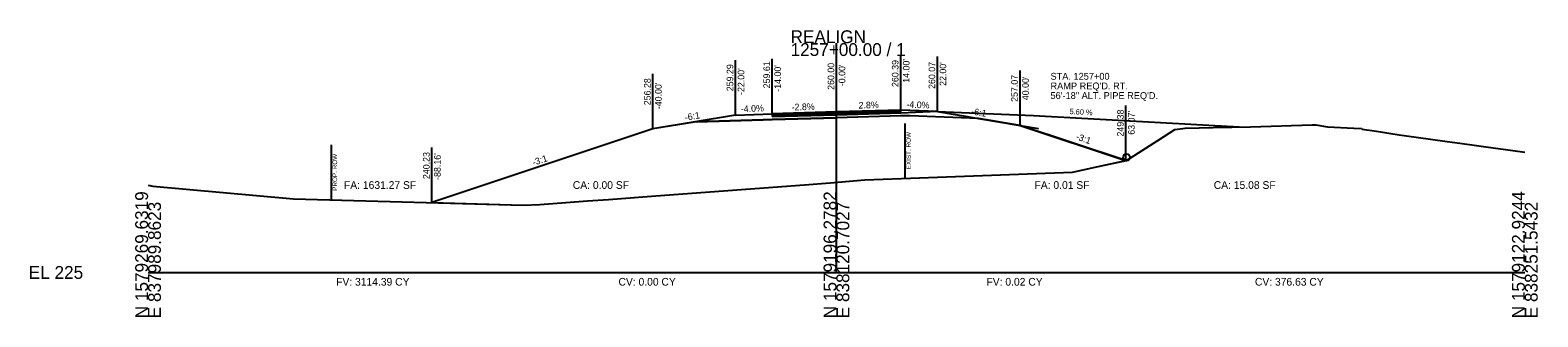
# Model space of a CAD drawing. Extents: x -26 to 6303, y -16 to 9563.
# Drawn here: x 2974.3 to 3302.8, y 8990.3 to 9052.8 of the extents above; entities that cross this region are included whole.
import ezdxf

# ---------------------------------------------------------------- set-up
doc = ezdxf.new("R2010")
doc.units = 0
for name, color, linetype in [('ASPHALT_19MM1', 7, 'Continuous'), ('ASPHALT_9_5MM1', 7, 'Continuous'), ('CONST_LV3', 7, 'Continuous'), ('CONST_PROF_LV1', 7, 'Continuous'), ('Draft_XS_Grid', 7, 'Continuous'), ('DTM_TEMP_DROP', 7, 'Continuous'), ('DTM_X_GROUND', 7, 'Continuous'), ('TRANS_BRIDGE', 7, 'Continuous'), ('XS_CELL', 7, 'Continuous'), ('XS_M_SHAPES_EARTHWORK', 7, 'Continuous'), ('XS_P_DRAINAGE', 7, 'Continuous'), ('XS_P_DRIVEWAY', 7, 'Continuous'), ('XS_P_GROUND', 7, 'Continuous'), ('XS_P_NULL_POINT', 7, 'Continuous'), ('XS_P_ROW', 7, 'Continuous'), ('XS_P_SHOULDER', 7, 'Continuous'), ('XS_P_SUBGRADE_GRANULAR', 7, 'Continuous'), ('XS_P_TX_CLEARZONE', 7, 'Continuous'), ('XS_P_TX_FS_BS', 7, 'Continuous'), ('XS_PLAN_CLEAR_ZONE', 7, 'Continuous'), ('XS_SHEET_EW_TX_AREA', 7, 'Continuous'), ('XS_SHEET_EW_TX_VOLUME', 7, 'Continuous'), ('XS_X_ROW', 7, 'Continuous')]:
    doc.layers.add(name, color=color, linetype=linetype)

msp = doc.modelspace()

# ---------------------------------------------------------------- linework, layer by layer
at = {"layer": 'ASPHALT_19MM1'}
msp.add_lwpolyline([(3136, 9034), (3136, 9034), (3136, 9034), (3150, 9034.39), (3150, 9034.39), (3164, 9034.79), (3164, 9034.79), (3164, 9035.06), (3150, 9034.66), (3150, 9034.66), (3136, 9034.27), (3136, 9034.27), (3136, 9034)], dxfattribs=at)
at = {"layer": 'ASPHALT_9_5MM1'}
msp.add_lwpolyline([(3136, 9034.48), (3136, 9034.48), (3136, 9034.48), (3150, 9034.87), (3150, 9034.87), (3164, 9035.26), (3164, 9035.26), (3164, 9035.39), (3150, 9035), (3150, 9035), (3136, 9034.61), (3136, 9034.61), (3136, 9034.48)], dxfattribs=at)
at = {"layer": 'CONST_LV3'}
for points in [[(3150, 9035), (3164, 9034.72)], [(3172, 9035.07), (3164, 9034.72), (3164, 9034.72)], [(3119.53, 9032.87), (3110, 9031.28)], [(3180.96, 9033.58), (3194, 9031.4)]]:
    msp.add_lwpolyline(points, dxfattribs=at)
at = {"layer": 'DTM_X_GROUND'}
msp.add_lwpolyline([(3000, 9019.04), (3001.05, 9018.78), (3031.7, 9016.03), (3081.64, 9014.7), (3085.4, 9014.85), (3095.72, 9015.59), (3100.34, 9015.93), (3110.61, 9016.69), (3143.07, 9019.07), (3148.65, 9019.53), (3156.22, 9020.17), (3164.2, 9020.47), (3201.46, 9021.88), (3207.05, 9023.08), (3213.18, 9024.4), (3220.06, 9028.8), (3223.76, 9031.15), (3225.46, 9031.38), (3226.01, 9031.46), (3232.11, 9031.6), (3240.2, 9031.77), (3253.63, 9032.18), (3254.31, 9032.2), (3254.46, 9032.17), (3257.04, 9031.77), (3262.74, 9031.44), (3264.42, 9031.36), (3264.58, 9031.25), (3267.71, 9030.81), (3272.6, 9030.04), (3276.32, 9029.49), (3283.05, 9028.57), (3285.83, 9028.16), (3293.58, 9027.12), (3295.28, 9026.87), (3300, 9026.24)], dxfattribs=at)
at = {"layer": 'XS_CELL'}
for p, q in [((3150, 9000), (3150, 9050)), ((3000, 9000), (3150, 9000)), ((3150, 9000), (3300, 9000))]:
    msp.add_line(p, q, dxfattribs=at)
at = {"layer": 'XS_M_SHAPES_EARTHWORK'}
msp.add_lwpolyline([(3061.84, 9015.23), (3081.64, 9014.7), (3085.4, 9014.85), (3095.72, 9015.59), (3100.34, 9015.93), (3110.61, 9016.69), (3143.07, 9019.07), (3148.65, 9019.53), (3156.22, 9020.17), (3164.2, 9020.47), (3201.46, 9021.88), (3207.05, 9023.08), (3213.07, 9024.38), (3190, 9032.07), (3180.96, 9033.58), (3166, 9034.17), (3164, 9034.12), (3150, 9033.73), (3136, 9033.33), (3134, 9033.28), (3119.53, 9032.87), (3110, 9031.28)], close=True, dxfattribs=at)
at = {"layer": 'XS_P_DRAINAGE'}
msp.add_circle((3213.21, 9025.08), 0.75, dxfattribs=at)
at = {"layer": 'XS_P_DRIVEWAY'}
for p, q in [((3172, 9035.07), (3192.94, 9034.23)), ((3192.94, 9034.23), (3237.76, 9031.72))]:
    msp.add_line(p, q, dxfattribs=at)
at = {"layer": 'XS_P_GROUND'}
for points in [[(3172, 9035.07), (3190, 9032.07), (3213.07, 9024.38)], [(3172, 9035.07), (3190, 9032.07), (3213.21, 9024.33)], [(3128, 9034.29), (3110, 9031.28), (3061.84, 9015.23)]]:
    msp.add_lwpolyline(points, dxfattribs=at)
at = {"layer": 'XS_P_ROW'}
msp.add_line((3040, 9015.81), (3040, 9027.81), dxfattribs=at)
at = {"layer": 'XS_P_SHOULDER'}
for points in [[(3172, 9035.07), (3172, 9035.07), (3164, 9035.39)], [(3128, 9034.29), (3128, 9034.29), (3136, 9034.61)]]:
    msp.add_lwpolyline(points, dxfattribs=at)
at = {"layer": 'XS_P_SUBGRADE_GRANULAR'}
for points in [[(3119.53, 9032.87), (3119.53, 9032.87), (3134, 9033.28), (3134, 9033.28), (3136, 9033.33)], [(3136, 9033.33), (3136, 9033.33), (3150, 9033.73)], [(3164, 9034.12), (3150, 9033.73), (3150, 9033.73)], [(3180.96, 9033.58), (3180.96, 9033.58), (3166, 9034.17), (3164, 9034.12), (3164, 9034.12)]]:
    msp.add_lwpolyline(points, dxfattribs=at)
at = {"layer": 'XS_P_TX_CLEARZONE'}
for p, q in [((3128, 9034.29), (3128, 9046.29)), ((3136, 9034.61), (3136, 9046.61)), ((3150, 9035), (3150, 9047)), ((3164, 9035.39), (3164, 9047.39)), ((3172, 9035.07), (3172, 9047.07)), ((3172, 9035.07), (3172, 9047.07)), ((3110, 9031.28), (3110, 9043.28)), ((3190, 9032.07), (3190, 9044.07)), ((3213.07, 9024.38), (3213.07, 9036.38)), ((3061.84, 9015.23), (3061.84, 9027.23))]:
    msp.add_line(p, q, dxfattribs=at)
at = {"layer": 'XS_PLAN_CLEAR_ZONE'}
msp.add_lwpolyline([(3136, 9034.27), (3136, 9034.27), (3136, 9034.27), (3150, 9034.66), (3150, 9034.66), (3164, 9035.06), (3164, 9035.06), (3164, 9035.26), (3150, 9034.87), (3150, 9034.87), (3136, 9034.48), (3136, 9034.48), (3136, 9034.27)], dxfattribs=at)
at = {"layer": 'XS_X_ROW'}
msp.add_line((3165.01, 9020.5), (3165.01, 9032.5), dxfattribs=at)

# ---------------------------------------------------------------- texts
at = {"layer": 'CONST_PROF_LV1'}
for p in [(3212.99, 9024.26), (3061.76, 9015.11)]:
    msp.add_text('X', height=0.24, dxfattribs=at).set_placement(p)
at = {"layer": 'Draft_XS_Grid'}
msp.add_text('-', height=0.0001, dxfattribs=at).set_placement((3000, 9000))
at = {"layer": 'DTM_TEMP_DROP'}
for p in [(3135.92, 9034.49), (3149.92, 9034.88), (3163.92, 9035.27)]:
    msp.add_text('X', height=0.24, dxfattribs=at).set_placement(p)
at = {"layer": 'TRANS_BRIDGE'}
for p in [(3212.99, 9024.26), (3061.76, 9015.11)]:
    msp.add_text('X', height=0.24, dxfattribs=at).set_placement(p)
at = {"layer": 'XS_CELL'}
for s, p in [('REALIGN', (3140, 9050)), ('1257+00.00 / 1', (3140, 9047.2)), ('EL 225', (2974, 8998.6))]:
    msp.add_text(s, height=2.8, dxfattribs=at).set_placement(p)
for s, p in [('N 1579269.6319', (3000, 8990)), ('E 837989.8623', (3002.8, 8990)), ('N 1579196.2782', (3150, 8990)), ('E 838120.7027', (3152.8, 8990)), ('N 1579122.9244', (3300, 8990)), ('E 838251.5432', (3302.8, 8990))]:
    msp.add_text(s, height=2.8, rotation=90, dxfattribs=at).set_placement(p)
at = {"layer": 'XS_P_DRIVEWAY'}
for s, p in [('STA. 1257+00', (3196.64, 9042.02)), ("RAMP REQ'D. RT.", (3196.64, 9039.92)), ('56\'-18" ALT. PIPE REQ\'D.', (3196.64, 9037.82))]:
    msp.add_text(s, height=1.5, dxfattribs=at).set_placement(p)
msp.add_text('5.60 %', height=1.2, rotation=356.7923, dxfattribs=at).set_placement((3200.78, 9034.54))
at = {"layer": 'XS_P_GROUND'}
for p in [(3109.92, 9031.16), (3193.92, 9031.28)]:
    msp.add_text('X', height=0.24, dxfattribs=at).set_placement(p)
at = {"layer": 'XS_P_NULL_POINT'}
for p in [(3171.92, 9034.95), (3189.92, 9031.95)]:
    msp.add_text('X', height=0.24, dxfattribs=at).set_placement(p)
at = {"layer": 'XS_P_ROW'}
msp.add_text('PROP. ROW', height=1, rotation=90, dxfattribs=at).set_placement((3041.2, 9017.81))
at = {"layer": 'XS_P_SHOULDER'}
for p in [(3171.92, 9034.95), (3127.92, 9034.17)]:
    msp.add_text('X', height=0.24, dxfattribs=at).set_placement(p)
at = {"layer": 'XS_P_SUBGRADE_GRANULAR'}
msp.add_text('X', height=0.24, dxfattribs=at).set_placement((3213.13, 9024.21))
at = {"layer": 'XS_P_TX_CLEARZONE'}
for s, p in [('259.29', (3127.52, 9039.52)), ('259.61', (3135.52, 9040.15)), ("-14.00'", (3137.92, 9039.4)), ('260.00', (3149.52, 9039.82)), ("-0.00'", (3151.92, 9040.61)), ('260.39', (3163.52, 9040.44)), ("14.00'", (3165.92, 9041.36)), ('260.07', (3171.52, 9040.02)), ("22.00'", (3173.92, 9040.68)), ('256.28', (3109.52, 9036.46)), ("-40.00'", (3111.92, 9035.6)), ("-22.00'", (3129.92, 9038.71)), ('257.07', (3189.52, 9037.2)), ("40.00'", (3191.92, 9037.56)), ('249.38', (3212.59, 9029.63)), ("63.07'", (3214.99, 9030.03)), ('240.23', (3061.36, 9020.36)), ("-88.16'", (3063.76, 9020.18))]:
    msp.add_text(s, height=1.44, rotation=90, dxfattribs=at).set_placement(p)
at = {"layer": 'XS_P_TX_FS_BS'}
for s, rotation, p in [('-6:1', 9.4642, (3117.08, 9033.07)), ('-4.0%', 2.2906, (3129.18, 9034.93)), ('-2.8%', 1.6039, (3140.25, 9035.32)), ('2.8%', 1.6039, (3154.84, 9035.73)), ('-4.0%', 357.7094, (3165.23, 9035.94)), ('-6:1', 350.5377, (3179.28, 9034.47)), ('-3:1', 339.784, (3202.04, 9029.08)), ('-3:1', 18.4332, (3084.01, 9023.25))]:
    msp.add_text(s, height=1.44, rotation=rotation, dxfattribs=at).set_placement(p)
at = {"layer": 'XS_SHEET_EW_TX_AREA'}
for s, p in [('FA: 1631.27 SF', (3042.69, 9018.22)), ('CA: 0.00 SF', (3092.56, 9018.22)), ('FA: 0.01 SF', (3193.16, 9018.22)), ('CA: 15.08 SF', (3232.22, 9018.22))]:
    msp.add_text(s, height=1.68, dxfattribs=at).set_placement(p)
at = {"layer": 'XS_SHEET_EW_TX_VOLUME'}
for s, p in [('FV: 3114.39 CY', (3040.98, 8997.12)), ('CV: 0.00 CY', (3102.51, 8997.12)), ('FV: 0.02 CY', (3182.69, 8997.12)), ('CV: 376.63 CY', (3241.19, 8997.12))]:
    msp.add_text(s, height=1.68, dxfattribs=at).set_placement(p)
at = {"layer": 'XS_X_ROW'}
msp.add_text('EXIST. ROW', height=1, rotation=90, dxfattribs=at).set_placement((3166.21, 9022.5))

doc.saveas('drawing.dxf')
